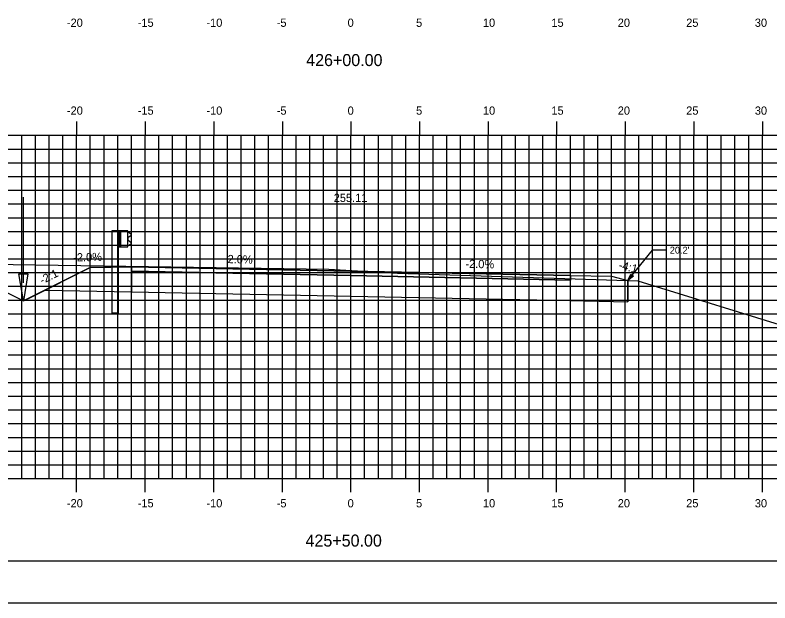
# Model space of a CAD drawing. Extents: x 1160718 to 1173142, y 616002 to 617630.
# Drawn here: x 1170603.2 to 1170658.2, y 616613.9 to 616656.7 of the extents above; entities that cross this region are included whole.
import ezdxf

# ---------------------------------------------------------------- set-up
doc = ezdxf.new("R2010")
doc.units = 0
for name, color, linetype in [('ANNOTATION', 7, 'Continuous'), ('BORDER', 7, 'Continuous'), ('D_Drainage_Ditch_Line', 7, 'Continuous'), ('D_Guardrail_Beam_Lt', 7, 'Continuous'), ('D_Roadway_Centerline', 7, 'Continuous'), ('D_Roadway_Centerline_Text', 7, 'Continuous'), ('D_Roadway_Edge_Shoulder', 7, 'Continuous'), ('D_Roadway_Edge_TW', 7, 'Continuous'), ('D_Roadway_Pavement', 7, 'Continuous'), ('D_Roadway_SlopeLines', 7, 'Continuous'), ('D_Roadway_SubGrade', 7, 'Continuous'), ('H_V ANNOTATION', 7, 'Continuous'), ('MAJOR', 7, 'Continuous'), ('MINOR', 7, 'Continuous'), ('PLOT BOUNDARY', 7, 'Continuous'), ('S_Roadway_Centerline', 7, 'Continuous'), ('SHADING', 7, 'Continuous')]:
    doc.layers.add(name, color=color, linetype=linetype)

msp = doc.modelspace()

# ---------------------------------------------------------------- linework, layer by layer
at = {"layer": 'ANNOTATION'}
for p, q in [((1170647.861, 616637.358), (1170649.664, 616639.56)), ((1170650.664, 616639.56), (1170649.664, 616639.56)), ((1170597.841, 616638.831), (1170603.786, 616635.859)), ((1170647.861, 616635.8), (1170647.861, 616637.358)), ((1170603.786, 616635.859), (1170604.407, 616636.169))]:
    msp.add_line(p, q, dxfattribs=at)
msp.add_lwpolyline([(1170648.274, 616637.666), (1170647.861, 616637.358), (1170648.081, 616637.824)], close=True, dxfattribs=at)
at = {"layer": 'BORDER'}
msp.add_line((1170552.664, 616616.928), (1170712.664, 616616.928), dxfattribs=at)
at = {"layer": 'D_Drainage_Ditch_Line'}
msp.add_line((1170603.786, 616637.171), (1170603.786, 616643.414), dxfattribs=at)
msp.add_lwpolyline([(1170603.458, 616637.827), (1170604.114, 616637.827), (1170603.786, 616635.859)], close=True, dxfattribs=at)
at = {"layer": 'D_Guardrail_Beam_Lt'}
for p, q in [((1170610.234, 616640.964), (1170610.234, 616634.964)), ((1170610.705, 616640.964), (1170610.234, 616640.964)), ((1170611.393, 616640.964), (1170610.705, 616640.964)), ((1170610.705, 616640.964), (1170610.705, 616639.798)), ((1170610.768, 616640.964), (1170610.768, 616639.798)), ((1170610.872, 616640.964), (1170610.872, 616639.798)), ((1170611.393, 616639.798), (1170611.393, 616640.964)), ((1170611.393, 616640.881), (1170611.467, 616640.866)), ((1170611.626, 616640.617), (1170611.431, 616640.48)), ((1170611.483, 616640.86), (1170611.626, 616640.76)), ((1170611.467, 616639.895), (1170611.393, 616639.881)), ((1170611.397, 616640.416), (1170611.397, 616640.346)), ((1170611.431, 616640.281), (1170611.626, 616640.145)), ((1170611.626, 616640.002), (1170611.483, 616639.902)), ((1170610.705, 616639.798), (1170611.393, 616639.798)), ((1170610.726, 616634.964), (1170610.726, 616639.798)), ((1170610.726, 616634.964), (1170610.234, 616634.964))]:
    msp.add_line(p, q, dxfattribs=at)
for centre, major_axis, start_param, end_param in [((1170611.476, 616640.416), (-0.0789, 0), 5.323254, 6.283185), ((1170611.459, 616640.826), (0.0417, 0), 0.959931, 1.376053), ((1170611.576, 616640.688), (0.0877, 0), 5.323254, 7.243116), ((1170611.476, 616640.346), (-0.0789, 0), 6.283185, 7.243116), ((1170611.459, 616639.936), (0.0417, 0), 4.907132, 5.323254), ((1170611.576, 616640.074), (0.0877, 0), 5.323254, 7.243116)]:
    msp.add_ellipse(centre, major_axis=major_axis, ratio=0.995501, start_param=start_param, end_param=end_param, dxfattribs=at)
at = {"layer": 'D_Roadway_Centerline'}
for points in [[(1170597.916, 616638.794), (1170603.786, 616635.859), (1170608.664, 616638.297)], [(1170603.786, 616635.859), (1170604.407, 616636.169), (1170608.664, 616638.297), (1170611.664, 616638.357), (1170627.664, 616638.037), (1170643.664, 616637.717), (1170646.664, 616637.657), (1170646.664, 616637.657), (1170647.861, 616637.358)]]:
    msp.add_lwpolyline(points, dxfattribs=at)
at = {"layer": 'D_Roadway_Edge_Shoulder'}
for points in [[(1170611.664, 616638.357), (1170611.664, 616638.024)], [(1170643.664, 616637.717), (1170643.664, 616637.384)]]:
    msp.add_lwpolyline(points, dxfattribs=at)
at = {"layer": 'D_Roadway_Edge_TW'}
msp.add_lwpolyline([(1170643.664, 616637.384), (1170643.664, 616637.717), (1170627.664, 616638.037), (1170611.664, 616638.357), (1170611.664, 616638.024), (1170627.664, 616637.704)], close=True, dxfattribs=at)
at = {"layer": 'D_Roadway_Pavement'}
msp.add_lwpolyline([(1170643.664, 616637.384), (1170643.664, 616637.384), (1170627.664, 616637.704), (1170611.664, 616638.024), (1170611.664, 616638.024), (1170627.664, 616637.704)], close=True, dxfattribs=at)
for points in [[(1170611.664, 616638.024), (1170611.664, 616638.024)], [(1170611.664, 616638.024), (1170611.664, 616638.024)], [(1170643.664, 616637.384), (1170643.664, 616637.384)], [(1170643.664, 616637.384), (1170643.664, 616637.384)]]:
    msp.add_lwpolyline(points, dxfattribs=at)
at = {"layer": 'D_Roadway_SlopeLines'}
for points in [[(1170608.664, 616638.297), (1170603.786, 616635.859)], [(1170646.664, 616637.657), (1170647.861, 616637.358)]]:
    msp.add_lwpolyline(points, dxfattribs=at)
at = {"layer": 'D_Roadway_SubGrade'}
for points in [[(1170611.664, 616636.524), (1170611.664, 616638.357), (1170608.664, 616638.297), (1170605.369, 616636.65)], [(1170643.664, 616635.884), (1170643.664, 616637.384), (1170627.664, 616637.704), (1170611.664, 616638.024), (1170611.664, 616636.524)], [(1170643.664, 616635.884), (1170643.664, 616637.717), (1170646.664, 616637.657), (1170647.861, 616637.358), (1170647.861, 616635.8)]]:
    msp.add_lwpolyline(points, dxfattribs=at)
at = {"layer": 'MAJOR'}
for p, q in [((1170607.664, 616648.93), (1170607.664, 616647.928)), ((1170612.664, 616648.93), (1170612.664, 616647.928)), ((1170617.664, 616648.93), (1170617.664, 616647.928)), ((1170622.664, 616648.93), (1170622.664, 616647.928)), ((1170627.664, 616648.93), (1170627.664, 616647.928)), ((1170632.664, 616648.93), (1170632.664, 616647.928)), ((1170637.664, 616648.93), (1170637.664, 616647.928)), ((1170642.664, 616648.93), (1170642.664, 616647.928)), ((1170647.664, 616648.93), (1170647.664, 616647.928)), ((1170652.664, 616648.93), (1170652.664, 616647.928)), ((1170657.664, 616648.93), (1170657.664, 616647.928)), ((1170557.664, 616647.928), (1170697.664, 616647.928)), ((1170557.664, 616647.928), (1170697.664, 616647.928)), ((1170607.664, 616622.928), (1170607.664, 616647.928)), ((1170612.664, 616622.928), (1170612.664, 616647.928)), ((1170617.664, 616622.928), (1170617.664, 616647.928)), ((1170622.664, 616622.928), (1170622.664, 616647.928)), ((1170627.664, 616622.928), (1170627.664, 616647.928)), ((1170632.664, 616622.928), (1170632.664, 616647.928)), ((1170637.664, 616622.928), (1170637.664, 616647.928)), ((1170642.664, 616622.928), (1170642.664, 616647.928)), ((1170647.664, 616622.928), (1170647.664, 616647.928)), ((1170652.664, 616622.928), (1170652.664, 616647.928)), ((1170657.664, 616622.928), (1170657.664, 616647.928)), ((1170557.664, 616642.928), (1170697.664, 616642.928)), ((1170557.664, 616637.928), (1170697.664, 616637.928)), ((1170557.664, 616632.928), (1170697.664, 616632.928)), ((1170557.664, 616627.928), (1170697.664, 616627.928)), ((1170557.664, 616622.928), (1170697.664, 616622.928)), ((1170557.664, 616622.928), (1170697.664, 616622.928)), ((1170607.664, 616621.926), (1170607.664, 616622.928)), ((1170612.664, 616621.926), (1170612.664, 616622.928)), ((1170617.664, 616621.926), (1170617.664, 616622.928)), ((1170622.664, 616621.926), (1170622.664, 616622.928)), ((1170627.664, 616621.926), (1170627.664, 616622.928)), ((1170632.664, 616621.926), (1170632.664, 616622.928)), ((1170637.664, 616621.926), (1170637.664, 616622.928)), ((1170642.664, 616621.926), (1170642.664, 616622.928)), ((1170647.664, 616621.926), (1170647.664, 616622.928)), ((1170652.664, 616621.926), (1170652.664, 616622.928)), ((1170657.664, 616621.926), (1170657.664, 616622.928))]:
    msp.add_line(p, q, dxfattribs=at)
at = {"layer": 'MINOR'}
for p, q in [((1170603.664, 616622.928), (1170603.664, 616647.928)), ((1170604.664, 616622.928), (1170604.664, 616647.928)), ((1170605.664, 616622.928), (1170605.664, 616647.928)), ((1170606.664, 616622.928), (1170606.664, 616647.928)), ((1170608.664, 616622.928), (1170608.664, 616647.928)), ((1170609.664, 616622.928), (1170609.664, 616647.928)), ((1170610.664, 616622.928), (1170610.664, 616647.928)), ((1170611.664, 616622.928), (1170611.664, 616647.928)), ((1170613.664, 616622.928), (1170613.664, 616647.928)), ((1170614.664, 616622.928), (1170614.664, 616647.928)), ((1170615.664, 616622.928), (1170615.664, 616647.928)), ((1170616.664, 616622.928), (1170616.664, 616647.928)), ((1170618.664, 616622.928), (1170618.664, 616647.928)), ((1170619.664, 616622.928), (1170619.664, 616647.928)), ((1170620.664, 616622.928), (1170620.664, 616647.928)), ((1170621.664, 616622.928), (1170621.664, 616647.928)), ((1170623.664, 616622.928), (1170623.664, 616647.928)), ((1170624.664, 616622.928), (1170624.664, 616647.928)), ((1170625.664, 616622.928), (1170625.664, 616647.928)), ((1170626.664, 616622.928), (1170626.664, 616647.928)), ((1170628.664, 616622.928), (1170628.664, 616647.928)), ((1170629.664, 616622.928), (1170629.664, 616647.928)), ((1170630.664, 616622.928), (1170630.664, 616647.928)), ((1170631.664, 616622.928), (1170631.664, 616647.928)), ((1170633.664, 616622.928), (1170633.664, 616647.928)), ((1170634.664, 616622.928), (1170634.664, 616647.928)), ((1170635.664, 616622.928), (1170635.664, 616647.928)), ((1170636.664, 616622.928), (1170636.664, 616647.928)), ((1170638.664, 616622.928), (1170638.664, 616647.928)), ((1170639.664, 616622.928), (1170639.664, 616647.928)), ((1170640.664, 616622.928), (1170640.664, 616647.928)), ((1170641.664, 616622.928), (1170641.664, 616647.928)), ((1170643.664, 616622.928), (1170643.664, 616647.928)), ((1170644.664, 616622.928), (1170644.664, 616647.928)), ((1170645.664, 616622.928), (1170645.664, 616647.928)), ((1170646.664, 616622.928), (1170646.664, 616647.928)), ((1170648.664, 616622.928), (1170648.664, 616647.928)), ((1170649.664, 616622.928), (1170649.664, 616647.928)), ((1170650.664, 616622.928), (1170650.664, 616647.928)), ((1170651.664, 616622.928), (1170651.664, 616647.928)), ((1170653.664, 616622.928), (1170653.664, 616647.928)), ((1170654.664, 616622.928), (1170654.664, 616647.928)), ((1170655.664, 616622.928), (1170655.664, 616647.928)), ((1170656.664, 616622.928), (1170656.664, 616647.928)), ((1170557.664, 616646.928), (1170697.664, 616646.928)), ((1170557.664, 616645.928), (1170697.664, 616645.928)), ((1170557.664, 616644.928), (1170697.664, 616644.928)), ((1170557.664, 616643.928), (1170697.664, 616643.928)), ((1170557.664, 616641.928), (1170697.664, 616641.928)), ((1170557.664, 616640.928), (1170697.664, 616640.928)), ((1170557.664, 616639.928), (1170697.664, 616639.928)), ((1170557.664, 616638.928), (1170697.664, 616638.928)), ((1170557.664, 616636.928), (1170697.664, 616636.928)), ((1170557.664, 616635.928), (1170697.664, 616635.928)), ((1170557.664, 616634.928), (1170697.664, 616634.928)), ((1170557.664, 616633.928), (1170697.664, 616633.928)), ((1170557.664, 616631.928), (1170697.664, 616631.928)), ((1170557.664, 616630.928), (1170697.664, 616630.928)), ((1170557.664, 616629.928), (1170697.664, 616629.928)), ((1170557.664, 616628.928), (1170697.664, 616628.928)), ((1170557.664, 616626.928), (1170697.664, 616626.928)), ((1170557.664, 616625.928), (1170697.664, 616625.928)), ((1170557.664, 616624.928), (1170697.664, 616624.928)), ((1170557.664, 616623.928), (1170697.664, 616623.928))]:
    msp.add_line(p, q, dxfattribs=at)
at = {"layer": 'PLOT BOUNDARY'}
msp.add_lwpolyline([(1170544.57, 616613.869), (1170714.57, 616613.869), (1170714.57, 616723.869), (1170544.57, 616723.869)], close=True, dxfattribs=at)
at = {"layer": 'S_Roadway_Centerline'}
msp.add_lwpolyline([(1170557.664, 616639.133), (1170564.795, 616639.41), (1170570.998, 616639.147), (1170598.104, 616638.815), (1170603.049, 616638.506), (1170626.043, 616638.184), (1170631.056, 616637.888), (1170648.586, 616637.335), (1170660.236, 616633.74)], dxfattribs=at)
at = {"layer": 'SHADING'}
for p, q in [((1170605.369, 616636.65), (1170611.664, 616636.524)), ((1170611.664, 616636.524), (1170643.664, 616635.884)), ((1170643.664, 616635.884), (1170647.861, 616635.8))]:
    msp.add_line(p, q, dxfattribs=at)

# ---------------------------------------------------------------- texts
at = {"layer": 'ANNOTATION'}
for s, rotation, p in [('-2.0%', 1.1458, (1170607.422, 616638.734)), ('2.0%', 358.8542, (1170618.667, 616638.618)), ('-2.0%', 358.8542, (1170636.007, 616638.271)), ('-4:1', 345.9638, (1170647.142, 616638.217)), ('-2:1', 26.5651, (1170605.154, 616637.061))]:
    msp.add_text(s, height=0.6, rotation=rotation, dxfattribs=at).set_placement(p)
msp.add_text("20.2'", height=0.5, dxfattribs=at).set_placement((1170650.914, 616639.31))
at = {"layer": 'D_Roadway_Centerline'}
for s, p in [('C', (1170627.658, 616638.037)), ('L', (1170627.664, 616638.03))]:
    msp.add_text(s, height=0.0146, dxfattribs=at).set_placement(p)
at = {"layer": 'D_Roadway_Centerline_Text'}
msp.add_text('255.11', height=0.6, dxfattribs=at).set_placement((1170626.411, 616643.069))
at = {"layer": 'H_V ANNOTATION'}
for s, height, p in [('-20', 0.6, (1170606.957, 616655.828)), ('-15', 0.6, (1170612.12, 616655.828)), ('-10', 0.6, (1170617.128, 616655.828)), ('-5', 0.6, (1170622.254, 616655.828)), ('0', 0.6, (1170627.423, 616655.828)), ('5', 0.6, (1170632.415, 616655.828)), ('10', 0.6, (1170637.289, 616655.828)), ('15', 0.6, (1170642.281, 616655.828)), ('20', 0.6, (1170647.118, 616655.828)), ('25', 0.6, (1170652.11, 616655.828)), ('30', 0.6, (1170657.112, 616655.828)), ('426+00.00', 0.875, (1170624.402, 616652.971)), ('-20', 0.6, (1170606.957, 616649.428)), ('-15', 0.6, (1170612.12, 616649.428)), ('-10', 0.6, (1170617.128, 616649.428)), ('-5', 0.6, (1170622.254, 616649.428)), ('0', 0.6, (1170627.423, 616649.428)), ('5', 0.6, (1170632.415, 616649.428)), ('10', 0.6, (1170637.289, 616649.428)), ('15', 0.6, (1170642.281, 616649.428)), ('20', 0.6, (1170647.118, 616649.428)), ('25', 0.6, (1170652.11, 616649.428)), ('30', 0.6, (1170657.112, 616649.428)), ('-20', 0.6, (1170606.957, 616620.828)), ('-15', 0.6, (1170612.12, 616620.828)), ('-10', 0.6, (1170617.128, 616620.828)), ('-5', 0.6, (1170622.254, 616620.828)), ('0', 0.6, (1170627.423, 616620.828)), ('5', 0.6, (1170632.415, 616620.828)), ('10', 0.6, (1170637.289, 616620.828)), ('15', 0.6, (1170642.281, 616620.828)), ('20', 0.6, (1170647.118, 616620.828)), ('25', 0.6, (1170652.11, 616620.828)), ('30', 0.6, (1170657.112, 616620.828)), ('425+50.00', 0.875, (1170624.355, 616617.971))]:
    msp.add_text(s, height=height, dxfattribs=at).set_placement(p)

doc.saveas('drawing.dxf')
